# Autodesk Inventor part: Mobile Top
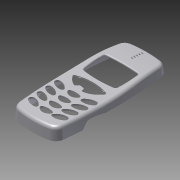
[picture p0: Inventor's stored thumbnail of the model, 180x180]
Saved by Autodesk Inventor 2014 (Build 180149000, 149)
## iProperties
Created: 2006-01
Part Number: Mobile Top
Document SubType Name: Modeling
Density: 1 g/cm^3
Material: Generic
Appearance: Default
Author: Autodesk
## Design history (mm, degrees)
sketch "Sketch1"
  geometry: L1 (-24, 54)-(24, 54); L2 (24, 54)-(24, -54); L3 (24, -54)-(-24, -54); L4 (-24, -54)-(-24, 54); A1 r 420.487 centre (396.487, -3.861) between (-20, 54) and (-21, -54); A2 r 420.487 centre (-396.487, -3.861) between (21, -54) and (20, 54); A3 r 90 centre (0, -33.75) between (20, 54) and (-20, 54); A4 r 80 centre (0, 23.195) between (-21, -54) and (21, -54); 1 further point
  constraints: 8 end point, 8 point on circle, 4 centre point, 4 point on line, 2 parallel, 2 tangent, 1 equal radius, 1 horizontal, 1 perpendicular
  dimensions: "d0" = 108 distance of L3.end L1.start; "d1" = 48 distance of L1.start L1.end; "d2" = 24 distance from line of point (0, 0) L4 (= 0.5 x d1); "d3" = 54 distance from line of point (0, 0) L1 (= 0.5 x d0); "d4" = 40 distance of A2.end A1.start; "d5" = 20 horizontal distance of point (0, 0) A1.start (= 0.5 x d4); "d6" = 42 distance of A2.start A1.end; "d7" = 90 radius of A3; "d8" = 80 radius of A4
extrude "Extrusion1" new body sketch "Sketch1" stored distance "d9" = 20; taper "d10" = 0 deg
fillet "Fillet2" dims "d70" = 8
sketch "Sketch7"
  geometry: L1 (-60.805, -3.5)-(-30.805, -3.5); L2 (-30.805, -3.5)-(-27.867, 0.545); L3 (-9.805, 0)-(56.25, 0); L4 (-56.805, -10)-(-56.805, 10) reference; L5 (56.25, -10)-(56.25, 10) reference; A1 r 5 centre (-23.821, -2.394) between (-23.915, 2.605) and (-27.867, 0.545); A2 r 48 centre (-23.015, -45.386) between (-10.546, 0.966) and (-23.915, 2.605); A3 r 1 centre (-10.805, 0) between (-9.805, 0) and (-10.546, 0.966)
  constraints: 6 end point, 6 point on circle, 3 centre point, 3 tangent, 1 horizontal, 1 horizontal alignment, 1 midpoint, 1 parallel
  dimensions: "d51" = 30 distance of L1.start L1.end; "d54" = 54 deg angle of L1 L2; "d55" = 5 distance of L1.end L2.end; "d56" = 3.5 distance between parallel lines of L1 L3; "d58" = 5 radius of A1; "d59" = 48 radius of A2; "d60" = 1 radius of A3; "d61" = 21 horizontal distance of L3.start L1.end; "d68" = 10 distance from line of L5.end L3
extrude_surface "ExtrusionSrf3" sketch "Sketch7" dims "d66" = 60, "d67" = 0
split "Split2"
fillet "Fillet1" dims "d69" = 0.5
sketch "Sketch12"
  geometry: L1 (-56.981, 8)-(-10.981, 8); L2 (-27.601, 0.545)-(-30.241, -3.088) reference; L3 (-31.05, -3.5)-(-49.773, -3.5) reference; L4 (-56.54, 2)-(-55.981, 10) reference; L5 (-55.981, 10)-(55.329, 10) reference; L6 (55.329, 10)-(56.028, 0) reference; L7 (56.028, 0)-(-8.808, 0) reference; A1 r 341.401 centre (-10.981, 349.401) between (-10.981, 8) and (19.482, 9.362); A2 r 160 centre (33.758, -150) between (56.329, 8.4) and (19.482, 9.362); A3 r 1 centre (-8.808, 1) between (-9.674, 0.5) and (-8.808, 0) reference; A4 r 1 centre (-10.54, 0) between (-9.674, 0.5) and (-10.281, 0.966) reference; A5 r 48 centre (-22.75, -45.386) between (-10.281, 0.966) and (-23.65, 2.605) reference; A6 r 5 centre (-23.556, -2.394) between (-23.65, 2.605) and (-27.601, 0.545) reference; A7 r 1 centre (-31.05, -2.5) between (-31.05, -3.5) and (-30.241, -3.088) reference; A8 r 1 centre (-49.773, -2.5) between (-50.725, -2.806) and (-49.773, -3.5) reference; A9 r 7 centre (-57.389, -4.948) between (-50.725, -2.806) and (-56.54, 2) reference
  constraints: 18 point on circle, 14 end point, 9 centre point, 4 horizontal, 3 tangent, 30 other
  dimensions: "d99" = 45 horizontal distance of L1.end L4.end; "d100" = 2 distance between parallel lines of L1 L5; "d101" = 1.6 vertical distance of L5.end A2.start; "d102" = 1 horizontal distance of L5.end A2.start; "d103" = 160 radius of A2; "d104" = 1 horizontal distance of L4.end L1.start
extrude_surface "ExtrusionSrf4" sketch "Sketch12" dims "d105" = 60, "d106" = 0
split "Split4"
fillet "Fillet7" dims "d108" = 3
feature "FaceDraft4" dims angle "d112" = 4 deg
shell "Shell3" dims "d113" = 1.5
sketch "Sketch13"
  geometry: L1 (-10.377, 0.699)-(-10.5, 0); L2 (-10.5, 0)-(10.5, 0); L3 (10.5, 0)-(10.377, 0.699); L4 (-14.135, 0)-(14.135, 0) reference; A1 r 40 centre (0, -36.707) between (8.85, 2.302) and (-8.85, 2.302); A2 r 2 centre (8.407, 0.352) between (10.377, 0.699) and (8.85, 2.302); A3 r 2 centre (-8.407, 0.352) between (-8.85, 2.302) and (-10.377, 0.699); 1 further point
  constraints: 6 end point, 6 point on circle, 4 tangent, 3 centre point, 1 collinear, 1 equal length, 1 equal radius, 1 horizontal
  dimensions: "d116" = 80 deg angle of L2 L1; "d118" = 40 radius of A1; "d569" = 2 radius of A2; "d570" = 0.6988 vertical distance of L1.start L1.end; "d571" = 21 distance of L2.end L1.end; "d572" = 10.5 distance of point (0, 0) L2.end (derived); "d573" = 0.6988 vertical distance of L2.end L3.end (derived)
extrude "Extrusion3" cut sketch "Sketch13" distance "d119" = 800; taper "d120" = 0 deg
sketch "Sketch14"
  geometry: A1 r 160 centre (0, -128.091) between (16.5, 31.056) and (-16.5, 31.056); A2 r 100 centre (0, 107.767) between (-16, 9.056) and (16, 9.056); A3 r 90 centre (73.052, 22.085) between (-16.5, 31.056) and (-16, 9.056); A4 r 90 centre (-73.052, 22.085) between (16, 9.056) and (16.5, 31.056); 3 further points
  constraints: 8 point on circle, 4 centre point, 2 horizontal alignment, 1 equal radius, 1 other
  dimensions: "d122" = 33 distance of A1.start A1.end; "d123" = 16.5 horizontal distance of point (0, 0) A1.end (derived); "d124" = 32 distance of A2.end A2.start; "d125" = 16 horizontal distance of point (0, 0) A2.start (derived); "d126" = 22 vertical distance of A2.start A1.end; "d127" = 160 radius of A1; "d128" = 100 radius of A2; "d129" = 90 radius of A3; "d130" = 25 vertical distance of A1.start point (10.5, 56.056)
extrude "Extrusion4" cut sketch "Sketch14" distance "d131" = 60; taper "d132" = 0 deg
fillet "Fillet9" dims "d133" = 2
fillet "Fillet10" dims "d134" = 1
sketch "Sketch15" dims "d138" = 22, "d139" = 20
  geometry: L1 (1, -9.972)-(0, -5.972); L2 (0, -5.972)-(-4.5, -5.172); L3 (-4.5, -5.172)-(-8, -8.163); A1 r 45 centre (0, -42) between (16.648, -0.193) and (-16.648, -0.193); 8 further points; 1 other entity
  constraints: 6 end point, 2 horizontal alignment, 2 point on circle, 2 vertical alignment, 1 centre point, 8 other
  dimensions: "d137" = 12 distance of point (0, 0) point (0, 12); "d140" = 45 radius of A1; "d141" = 42 distance of point (0, 0) A1.centre; "d164" = 1 horizontal distance of point (0, 0) L1.start; "d165" = 8 horizontal distance of point (0, 0) L3.end; "d166" = 4 vertical distance of L1.start L1.end; "d167" = 4.5 horizontal distance of L1.end L2.end; "d168" = 0.8 vertical distance of L1.end L2.end
extrude "Extrusion7" cut sketch "Sketch15" stored distance "d169" = 1.5; taper "d170" = 0 deg
fillet "Fillet12" dims "d171" = 1.2
workplane "Work Plane7"
sketch "Sketch17"
  geometry: L1 (-15.808, -1.477)-(15.808, -1.477); A1 r 18.61 centre (0.054, 8.614) between (-8, -8.163) and (1, -9.972)
  constraints: 2 end point, 2 point on circle, 1 centre point, 1 horizontal, 3 other
extrude "Extrusion8" cut sketch "Sketch17" distance "d173" = 2.5; taper "d174" = 0 deg
workplane "Work Plane8"
sketch "Sketch18" dims "d176" = 1
  geometry: A1 r 18.31 centre (-0.007, -19.291) between (1, -1.008) and (-8, -2.818); A2 r 19.31 centre (-0.007, -19.291) between (1.055, -0.01) and (-8.435, -1.917); 8 further points
  constraints: 4 point on circle, 2 centre point, 2 concentric, 2 horizontal alignment, 19 other
extrude "Extrusion9" cut sketch "Sketch18" distance "d177" = 0.5; taper "d178" = 0 deg
sketch "Sketch19"
  geometry: L1 (-1, 1.008)-(-0.189, 4.254) reference; L2 (-12.654, 12.165)-(-12.384, 11.797); L3 (-12.384, 11.797)-(-10.52, 12.182); L4 (-10.52, 12.182)-(-10.373, 12.769); A1 r 45 centre (0, -31.019) between (15.233, 11.324) and (-15.233, 11.324) reference
  constraints: 6 end point, 2 point on circle, 1 parallel
extrude "Extrusion10" join sketch "Sketch19" distance "d179" = 0.5; taper "d180" = 0 deg
mirror "Mirror1"
sketch "Sketch20"
  geometry: L1 (0, 0)-(41.879, 0) reference; A1 r 2.5 centre (3, -3) between (3.096, -0.502) and (1.347, -4.876); A2 r 12 centre (2.633, -12.493) between (11.888, -4.854) and (3.096, -0.502); A3 r 12 centre (9.281, 4.127) between (1.347, -4.876) and (10.715, -7.787); A4 r 1.8 centre (10.5, -6) between (10.715, -7.787) and (11.888, -4.854); A5 r 14 centre (20.939, -16.649) between (25.738, -3.497) and (16.141, -3.497); A6 r 1.6 centre (16.689, -5) between (16.141, -3.497) and (15.43, -5.987); A7 r 7 centre (20.939, -1.669) between (15.43, -5.987) and (26.449, -5.987); A8 r 1.6 centre (25.189, -5) between (26.449, -5.987) and (25.738, -3.497); A9 r 1.8 centre (10.818, -15) between (11.033, -16.787) and (12.206, -13.854); A10 r 12 centre (9.599, -4.873) between (1.665, -13.876) and (11.033, -16.787); A11 r 2.5 centre (3.318, -12) between (3.414, -9.502) and (1.665, -13.876); A12 r 12 centre (2.951, -21.493) between (12.206, -13.854) and (3.414, -9.502); A13 r 2.5 centre (3.831, -21) between (3.928, -18.502) and (2.178, -22.876); A14 r 12 centre (3.465, -30.493) between (12.719, -22.854) and (3.928, -18.502); A15 r 12 centre (10.113, -13.873) between (2.178, -22.876) and (11.546, -25.787); A16 r 1.8 centre (11.331, -24) between (11.546, -25.787) and (12.719, -22.854); A17 r 12 centre (37.198, -39.499) between (37.373, -27.5) and (27.95, -31.853); A18 r 2.5 centre (37.337, -30) between (39.008, -31.859) and (37.373, -27.5); A19 r 12 centre (30.987, -22.934) between (29.046, -34.776) and (39.008, -31.859); A20 r 1.8 centre (29.337, -33) between (27.95, -31.853) and (29.046, -34.776); A21 r 2.5 centre (4.542, -30) between (4.638, -27.502) and (2.889, -31.876); A22 r 12 centre (10.823, -22.873) between (2.889, -31.876) and (12.257, -34.787); A23 r 1.8 centre (12.042, -33) between (12.257, -34.787) and (13.43, -31.854); A24 r 12 centre (4.175, -39.493) between (13.43, -31.854) and (4.638, -27.502); A25 r 414.55 centre (417.426, 7.12) between (3, -3) and (4.542, -30); A26 r 417.487 centre (417.426, 7.12) between (0, 0) and (2.281, -37.041) reference; A27 r 7 centre (20.939, -28.669) between (15.43, -32.987) and (26.449, -32.987); A28 r 1.6 centre (25.189, -32) between (26.449, -32.987) and (25.738, -30.497); A29 r 14 centre (20.939, -43.649) between (25.738, -30.497) and (16.141, -30.497); A30 r 1.6 centre (16.689, -32) between (16.141, -30.497) and (15.43, -32.987); A31 r 1.6 centre (16.689, -14) between (16.141, -12.497) and (15.43, -14.987); A32 r 1.6 centre (25.189, -14) between (26.449, -14.987) and (25.738, -12.497); A33 r 7 centre (20.939, -10.669) between (15.43, -14.987) and (26.449, -14.987); A34 r 14 centre (20.939, -25.649) between (25.738, -12.497) and (16.141, -12.497); A35 r 1.6 centre (16.689, -23) between (16.141, -21.497) and (15.43, -23.987); A36 r 1.6 centre (25.189, -23) between (26.449, -23.987) and (25.738, -21.497); A37 r 7 centre (20.939, -19.669) between (15.43, -23.987) and (26.449, -23.987); A38 r 14 centre (20.939, -34.649) between (25.738, -21.497) and (16.141, -21.497); A39 r 1.8 centre (30.047, -24) between (28.66, -22.853) and (29.756, -25.776); A40 r 12 centre (37.909, -30.499) between (38.084, -18.5) and (28.66, -22.853); A41 r 12 centre (31.697, -13.934) between (29.756, -25.776) and (39.718, -22.859); A42 r 2.5 centre (38.047, -21) between (39.718, -22.859) and (38.084, -18.5); A43 r 1.8 centre (30.561, -15) between (29.174, -13.853) and (30.27, -16.776); A44 r 12 centre (32.211, -4.934) between (30.27, -16.776) and (40.232, -13.859); A45 r 12 centre (38.422, -21.499) between (38.597, -9.5) and (29.174, -13.853); A46 r 2.5 centre (38.561, -12) between (40.232, -13.859) and (38.597, -9.5); A47 r 1.8 centre (30.879, -6) between (29.491, -4.853) and (30.587, -7.776); A48 r 12 centre (32.528, 4.066) between (30.587, -7.776) and (40.55, -4.859); A49 r 12 centre (38.74, -12.499) between (38.915, -0.5) and (29.491, -4.853); A50 r 2.5 centre (38.879, -3) between (40.55, -4.859) and (38.915, -0.5); A51 r 414.55 centre (-375.547, 7.12) between (37.337, -30) and (38.879, -3); A52 r 417.487 centre (-375.547, 7.12) between (39.597, -37.041) and (41.879, 0) reference; 1 further point
  constraints: 104 point on circle, 50 centre point, 48 tangent, 9 vertical alignment, 7 horizontal alignment, 4 equal radius, 2 coincident, 2 concentric
  dimensions: "d181" = 12 radius of A2; "d182" = 12 radius of A3 (derived); "d183" = 2.5 radius of A1; "d184" = 1.8 radius of A4; "d185" = 7.5 horizontal distance of A4.centre A1.centre; "d186" = 3 vertical distance of A4.centre A1.centre; "d187" = 8.5 distance of A8.centre A6.centre; "d188" = 1.6 radius of A6; "d189" = 14 radius of A5; "d190" = 7 radius of A7; "d193" = 12 radius of A12; "d194" = 12 radius of A10 (derived); "d195" = 2.5 radius of A11; "d196" = 1.8 radius of A9; "d197" = 7.5 horizontal distance of A9.centre A11.centre (derived); "d198" = 3 vertical distance of A9.centre A11.centre (derived); "d199" = 12 radius of A14; "d200" = 12 radius of A15 (derived); "d201" = 2.5 radius of A13; "d202" = 1.8 radius of A16; "d203" = 7.5 horizontal distance of A16.centre A13.centre (derived); "d204" = 3 vertical distance of A16.centre A13.centre (derived); "d205" = 8 horizontal distance of A18.centre A20.centre; "d206" = 3 vertical distance of A18.centre A20.centre; "d207" = 1.8 radius of A20; "d208" = 12 radius of A17; "d209" = 12 radius of A19; "d210" = 2.5 radius of A18; "d211" = 12 radius of A24; "d212" = 12 radius of A22 (derived); "d213" = 2.5 radius of A21; "d214" = 1.8 radius of A23; "d215" = 7.5 horizontal distance of A23.centre A21.centre (derived); "d216" = 3 vertical distance of A23.centre A21.centre (derived); "d217" = 3 distance from line of L1 A1.centre; "d218" = 9 vertical distance of A9.centre A4.centre; "d219" = 9 vertical distance of A16.centre A9.centre; "d220" = 9 vertical distance of A23.centre A16.centre; "d222" = 3 horizontal distance of L1.start A1.centre; "d223" = 8.5 distance of A28.centre A30.centre (derived); "d224" = 1.6 radius of A30 (derived); "d225" = 14 radius of A29 (derived); "d226" = 7 radius of A27 (derived); "d227" = 8.5 distance of A32.centre A31.centre (derived); "d228" = 1.6 radius of A31 (derived); "d229" = 14 radius of A34 (derived); "d230" = 7 radius of A33 (derived); "d231" = 8.5 distance of A36.centre A35.centre (derived); "d232" = 1.6 radius of A35 (derived); "d233" = 14 radius of A38 (derived); "d234" = 7 radius of A37 (derived); "d235" = 9 distance of A32.centre A8.centre; "d236" = 9 distance of A36.centre A32.centre (derived); "d237" = 9 distance of A28.centre A36.centre (derived); "d238" = 5 distance from line of L1 A6.centre; "d239" = 8 horizontal distance of A42.centre A39.centre; "d240" = 3 vertical distance of A42.centre A39.centre; "d241" = 1.8 radius of A39; "d242" = 12 radius of A40; "d243" = 12 radius of A41; "d244" = 2.5 radius of A42; "d245" = 8 horizontal distance of A46.centre A43.centre; "d246" = 3 vertical distance of A46.centre A43.centre; "d247" = 1.8 radius of A43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
extrude "Extrusion12" cut sketch "Sketch20" stored distance "d259" = 10; taper "d260" = 0 deg
sketch "Sketch21"
  geometry: L1 (52.823, 8.86)-(53.02, 11.352); L2 (53.02, 11.352)-(40.06, 12.376); L3 (40.06, 12.376)-(39.863, 9.883); L4 (-68.28, 0)-(91.232, 0) reference; A1 r 158.5 centre (33.758, -150) between (53.437, 7.274) and (32.867, 8.497) reference; A2 r 160 centre (33.758, -150) between (53.623, 8.762) and (33.868, 10) reference; A3 r 90 centre (53.409, 98.858) between (39.863, 9.883) and (52.823, 8.86)
  constraints: 8 point on circle, 6 end point, 3 centre point, 2 perpendicular, 1 parallel, 8 other
  dimensions: "d261" = 90 radius of A3; "d262" = 13 distance of L1.end L2.end; "d264" = 2.5 distance of L1.start L1.end; "d266" = 0.8 horizontal distance of A2.start L1.start
revolve "Revolution1" sketch "Sketch21" stored, may be unused: angle "d265" = 90 deg
sketch "Sketch22"
  geometry: L1 (39.983, 8.378)-(51.947, 7.453); L2 (39.983, 8.378)-(39.998, 8.577); L3 (39.998, 8.577)-(51.945, 7.654); L4 (51.945, 7.654)-(51.947, 7.453); A1 r 158.5 centre (33.758, -150) between (53.437, 7.274) and (31.867, 8.489) reference
  constraints: 8 end point, 4 point on circle, 1 centre point, 1 parallel, 1 perpendicular, 4 other
  dimensions: "d267" = 12 distance of L1.start L1.end; "d268" = 1.5 distance of L1.end A1.start; "d575" = 0.2 distance between parallel lines of L1 L3; "d576" = 95 deg angle of L3 L4
extrude "Extrusion13" cut sketch "Sketch22" stored distance "d270" = 10; taper "d271" = 0 deg
sketch "Sketch23"
  geometry: L1 (10, 0)-(0, 0) reference; L2 (10, -11.983)-(0, -11.983) reference; L3 (-4, 0)-(14, 0); L4 (14, 0)-(12, -11.983); L5 (12, -11.983)-(-2, -11.983); L6 (-2, -11.983)-(-4, 0); 1 further point
  constraints: 8 end point, 2 point on line, 1 equal length, 1 parallel
  dimensions: "d272" = 18 distance of L3.start L3.end; "d273" = 9 horizontal distance of point (5, -51.201) L3.start (derived); "d274" = 14 distance of L4.end L5.end; "d275" = 7 horizontal distance of point (5, -51.201) L5.end (derived)
extrude "Extrusion14" cut sketch "Sketch23" stored distance "d276" = 10; taper "d277" = 0 deg
delete_face "Delete Face1"
fillet "Fillet13" dims "d278" = 2
sketch "Sketch24" dims "d280" = 1, "d281" = 0.5, "d285" = 1, "d286" = 0.5, "d287" = 1, "d288" = 0.5, "d289" = 1, "d290" = 0.5, "d291" = 1, "d292" = 0.5
  geometry: L1 (0, -68.275)-(0, 91.177) reference; L2 (6.639, 51.93)-(-6.639, 51.93) reference; 7 further points; 5 other entities
  constraints: 5 vertical alignment, 1 point on line, 10 other
  dimensions: "d293" = 2.5 distance of point (0, 48.647) point (0, 51.147); "d294" = 2.5 distance of point (0, 46.147) point (0, 48.647) (derived); "d295" = 2.5 distance of point (0, 46.147) point (0, 43.647) (derived); "d296" = 2.5 distance of point (0, 43.647) point (0, 41.147) (derived); "d552" = 0.8 distance from line of L2 point (0, 51.147)
extrude "Extrusion44" cut sketch "Sketch24" stored distance "d553" = 10; taper "d554" = 0 deg
sketch "Sketch26" dims "d301" = 0.8, "d302" = 0.8
  geometry: L1 (47.842, -0.062)-(47.842, 0.011); L2 (0.8, 0.011)-(0.796, 0.318); L3 (0.796, 0.318)-(0.794, -1.154); L4 (47.842, -0.062)-(47.842, -1.154); L5 (13.53, 64.607)-(14.113, 64.674); L6 (14.113, 64.674)-(14.113, 65.481); L7 (14.113, 65.481)-(13.821, 65.447); L8 (35.12, 64.606)-(32.991, 64.859); L9 (32.991, 64.859)-(32.991, 65.659); L10 (32.991, 65.659)-(34.821, 65.447); L11 (1.588, -1.154)-(0.085, -1.154) reference; L12 (48.557, -1.154)-(47.053, -1.154) reference; 16 further points
  constraints: 20 end point, 2 parallel, 2 point on line, 1 collinear, 1 vertical, 38 other
  dimensions: "d303" = 0.8 distance of L8.end L9.end
extrude "Extrusion17" cut sketch "Sketch26" distance "d304" = 0.6; taper "d305" = 0 deg
fillet "Fillet15" dims "d306" = 1
sketch "Sketch71"
  geometry: L1 (-21.544, -71.503)-(-23.028, -53.188); L2 (-23.028, -53.188)-(-21.428, -53.058); L3 (-21.428, -53.058)-(-19.944, -71.373); L4 (-19.944, -71.373)-(-21.544, -71.503); 2 further points
  constraints: 8 end point, 2 parallel, 1 midpoint, 1 perpendicular
  dimensions: "d588" = 1.6 horizontal distance of L1.end L2.end
extrude "Extrusion47" cut sketch "Sketch71" distance "d589" = 0.8; taper "d590" = 0 deg
mirror "Mirror2"
fillet "Fillet33" dims "d591" = 0.8
workplane "Work Plane17"
sketch "Sketch62" dims "d460" = 1.5
  geometry: 20 further points
  constraints: 40 other
extrude "Extrusion43" cut sketch "Sketch62" stored distance "d461" = 0.4; taper "d462" = 0 deg
body "Solid1"
body "Srf1"
body "Srf2"
other parameters: "d175" = 0
